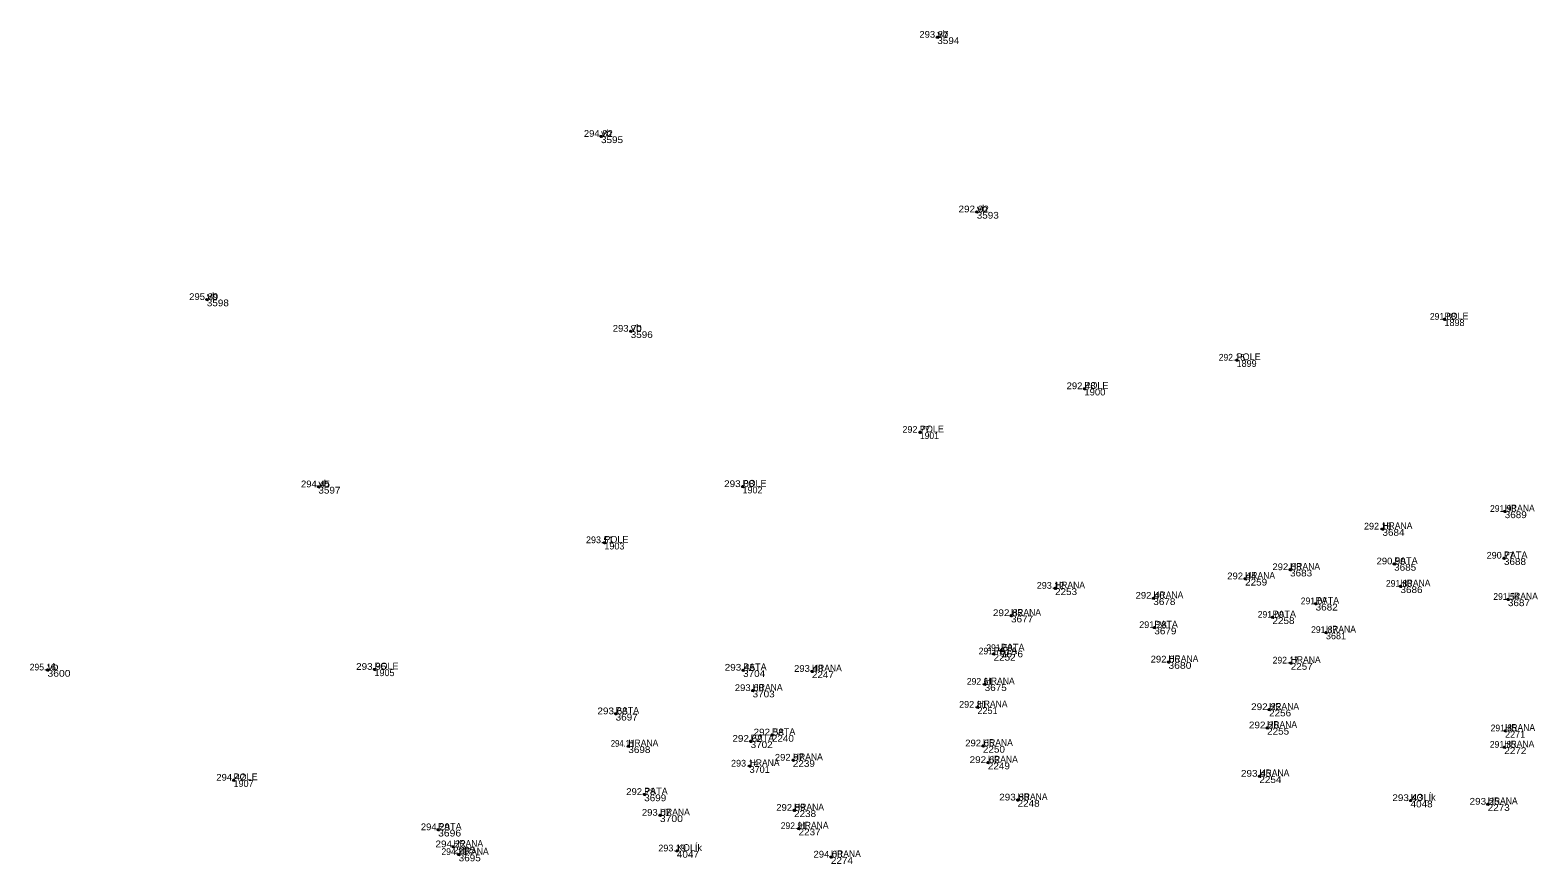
# Model space of a CAD drawing. Extents: x -565336 to -561834, y -1146819 to -1145270.
# Drawn here: x -563913.6 to -563837.5, y -1145806.3 to -1145764.2 of the extents above; entities that cross this region are included whole.
import ezdxf
from ezdxf.enums import TextEntityAlignment as Align

# ---------------------------------------------------------------- set-up
doc = ezdxf.new("R2010")
doc.units = 0
doc.header["$LTSCALE"] = 0.14
doc.header["$PDMODE"] = 32
doc.header["$PDSIZE"] = 0.07
for name, color, linetype in [('40', 7, 'Continuous'), ('43', 7, 'Continuous'), ('44', 7, 'Continuous'), ('45', 7, 'Continuous')]:
    doc.layers.add(name, color=color, linetype=linetype)

msp = doc.modelspace()

# ---------------------------------------------------------------- linework, layer by layer
at = {"layer": '40'}
for p in [(-563867.83, -1145764.59), (-563884.8, -1145769.59), (-563865.84, -1145773.4), (-563904.69, -1145777.82), (-563842.24, -1145778.82), (-563883.3, -1145779.42), (-563852.73, -1145780.88), (-563860.41, -1145782.32), (-563868.71, -1145784.52), (-563899.06, -1145787.27), (-563877.66, -1145787.26), (-563839.2, -1145788.51), (-563845.37, -1145789.4), (-563884.63, -1145790.09), (-563844.78, -1145791.16), (-563839.24, -1145790.87), (-563852.3, -1145791.91), (-563850.03, -1145791.45), (-563861.89, -1145792.39), (-563844.46, -1145792.29), (-563856.93, -1145792.89), (-563848.74, -1145793.17), (-563839.04, -1145792.95), (-563864.11, -1145793.77), (-563850.92, -1145793.85), (-563856.88, -1145794.37), (-563848.22, -1145794.62), (-563864.99, -1145795.7), (-563864.62, -1145795.53), (-563912.73, -1145796.51), (-563896.23, -1145796.48), (-563877.63, -1145796.52), (-563856.17, -1145796.11), (-563850, -1145796.16), (-563874.16, -1145796.58), (-563865.44, -1145797.23), (-563877.15, -1145797.55), (-563884.06, -1145798.72), (-563865.8, -1145798.39), (-563851.09, -1145798.51), (-563851.19, -1145799.43), (-563839.18, -1145799.58), (-563883.42, -1145800.36), (-563877.25, -1145800.11), (-563876.18, -1145799.79), (-563865.53, -1145800.34), (-563875.12, -1145801.06), (-563839.22, -1145800.41), (-563877.3, -1145801.36), (-563865.28, -1145801.18), (-563851.58, -1145801.87), (-563903.34, -1145802.07), (-563882.62, -1145802.79), (-563863.78, -1145803.07), (-563843.95, -1145803.1), (-563840.06, -1145803.28), (-563881.83, -1145803.84), (-563875.06, -1145803.59), (-563893.02, -1145804.57), (-563874.83, -1145804.51), (-563892.26, -1145805.43), (-563880.97, -1145805.64), (-563891.98, -1145805.82), (-563873.2, -1145805.95)]:
    msp.add_point(p, dxfattribs=at)

# ---------------------------------------------------------------- texts
at = {"layer": '43'}
for s, width, p in [('3594', 1.1, (-563867.83, -1145764.93)), ('3595', 1.1, (-563884.8, -1145769.93)), ('3593', 1.1, (-563865.84, -1145773.74)), ('3598', 1.1, (-563904.69, -1145778.16)), ('3596', 1.1, (-563883.3, -1145779.76)), ('1900', 1.05, (-563860.41, -1145782.66)), ('1901', 0.95, (-563868.71, -1145784.86)), ('3597', 1.1, (-563899.06, -1145787.61)), ('3689', 1.1, (-563839.2, -1145788.85)), ('3684', 1.1, (-563845.37, -1145789.74)), ('3685', 1.1, (-563844.78, -1145791.5)), ('3688', 1.1, (-563839.24, -1145791.21)), ('2259', 1.1, (-563852.3, -1145792.25)), ('3683', 1.1, (-563850.03, -1145791.79)), ('2253', 1.1, (-563861.89, -1145792.73)), ('3686', 1.1, (-563844.46, -1145792.63)), ('3678', 1.1, (-563856.93, -1145793.23)), ('3682', 1.1, (-563848.74, -1145793.51)), ('3687', 1.1, (-563839.04, -1145793.29)), ('3677', 1.1, (-563864.11, -1145794.11)), ('2258', 1.1, (-563850.92, -1145794.19)), ('3679', 1.1, (-563856.88, -1145794.71)), ('2252', 1.1, (-563864.99, -1145796.04)), ('3676', 1.1, (-563864.62, -1145795.87)), ('3600', 1.15, (-563912.73, -1145796.85)), ('3704', 1.1, (-563877.63, -1145796.86)), ('3680', 1.15, (-563856.17, -1145796.45)), ('2257', 1.1, (-563850, -1145796.5)), ('2247', 1.1, (-563874.16, -1145796.92)), ('3675', 1.1, (-563865.44, -1145797.57)), ('3703', 1.1, (-563877.15, -1145797.89)), ('3697', 1.1, (-563884.06, -1145799.06)), ('2256', 1.1, (-563851.09, -1145798.85)), ('2255', 1.1, (-563851.19, -1145799.77)), ('3702', 1.1, (-563877.25, -1145800.45)), ('2240', 1.1, (-563876.18, -1145800.13)), ('3698', 1.1, (-563883.42, -1145800.7)), ('2239', 1.1, (-563875.12, -1145801.4)), ('2250', 1.1, (-563865.53, -1145800.68)), ('2272', 1.1, (-563839.22, -1145800.75)), ('2249', 1.1, (-563865.28, -1145801.52)), ('2254', 1.1, (-563851.58, -1145802.21)), ('3699', 1.1, (-563882.62, -1145803.13)), ('2248', 1.1, (-563863.78, -1145803.41)), ('4048', 1.1, (-563843.95, -1145803.44)), ('2273', 1.1, (-563840.06, -1145803.62)), ('3700', 1.15, (-563881.83, -1145804.18)), ('2238', 1.1, (-563875.06, -1145803.93)), ('3696', 1.15, (-563893.02, -1145804.91)), ('2237', 1.1, (-563874.83, -1145804.85)), ('2235', 1.1, (-563892.26, -1145805.77)), ('4047', 1.1, (-563880.97, -1145805.98)), ('3695', 1.1, (-563891.98, -1145806.16)), ('2274', 1.1, (-563873.2, -1145806.29))]:
    msp.add_text(s, height=0.34, dxfattribs=dict(at, width=width)).set_placement(p)
for s, p in [('1898', (-563842.24, -1145779.16)), ('1899', (-563852.73, -1145781.22)), ('1902', (-563877.66, -1145787.6)), ('1903', (-563884.63, -1145790.43)), ('3681', (-563848.22, -1145794.96)), ('1905', (-563896.23, -1145796.82)), ('2251', (-563865.8, -1145798.73)), ('2271', (-563839.18, -1145799.92)), ('3701', (-563877.3, -1145801.7)), ('1907', (-563903.34, -1145802.41))]:
    msp.add_text(s, height=0.34, dxfattribs=at).set_placement(p)
at = {"layer": '44'}
for s, width, p in [('293.87', 1.05, (-563868.0055, -1145764.614)), ('294.82', 1.05, (-563884.935, -1145769.614)), ('292.92', 1.1, (-563865.9955, -1145773.424)), ('295.89', 1.05, (-563904.8495, -1145777.844)), ('291.88', 0.95, (-563842.3165, -1145778.844)), ('293.70', 1.05, (-563883.4755, -1145779.444)), ('292.16', 0.95, (-563852.97, -1145780.904)), ('292.48', 1.05, (-563860.576, -1145782.344)), ('294.45', 1.05, (-563899.206, -1145787.294)), ('293.08', 1.1, (-563877.8235, -1145787.284)), ('291.98', 0.95, (-563839.2815, -1145788.534)), ('292.08', 1.05, (-563850.191, -1145791.474)), ('290.90', 1.05, (-563844.9355, -1145791.184)), ('292.44', 1.05, (-563852.47, -1145791.934)), ('292.40', 1.05, (-563857.095, -1145792.914)), ('291.80', 0.95, (-563844.535, -1145792.314)), ('291.54', 0.95, (-563839.1165, -1145792.974)), ('292.82', 1.1, (-563864.26, -1145793.794)), ('291.07', 0.95, (-563848.8285, -1145793.194)), ('291.09', 0.95, (-563851.0005, -1145793.874)), ('291.87', 0.95, (-563848.3085, -1145794.644)), ('291.78', 0.95, (-563865.08, -1145795.724)), ('291.59', 0.95, (-563864.6965, -1145795.554)), ('295.16', 0.95, (-563912.9645, -1145796.534)), ('293.95', 1.1, (-563896.3935, -1145796.504)), ('293.45', 1.1, (-563877.7935, -1145796.544)), ('293.48', 1.05, (-563874.3285, -1145796.604)), ('292.06', 1.05, (-563856.335, -1145796.134)), ('292.17', 0.95, (-563850.248, -1145796.184)), ('293.60', 1.05, (-563877.3175, -1145797.574)), ('292.61', 0.95, (-563865.68, -1145797.254)), ('293.63', 1.1, (-563884.2155, -1145798.744)), ('292.22', 1.1, (-563851.231, -1145798.534)), ('292.58', 1.1, (-563876.337, -1145799.814)), ('292.28', 1.1, (-563851.3415, -1145799.454)), ('291.85', 0.95, (-563839.251, -1145799.604)), ('294.11', 0.85, (-563883.7145, -1145800.384)), ('292.62', 1.1, (-563877.4055, -1145800.134)), ('292.65', 1.05, (-563865.691, -1145800.364)), ('291.85', 0.95, (-563839.291, -1145800.434)), ('292.97', 1.05, (-563875.2985, -1145801.084)), ('292.62', 1.1, (-563865.4355, -1145801.204)), ('294.42', 1.05, (-563903.4805, -1145802.094)), ('293.45', 1.1, (-563851.7435, -1145801.894)), ('292.78', 1.05, (-563882.7945, -1145802.814)), ('292.89', 1.05, (-563875.225, -1145803.614)), ('293.80', 1.1, (-563863.942, -1145803.094)), ('293.43', 1.1, (-563844.1055, -1145803.124)), ('293.25', 1.1, (-563840.2085, -1145803.304)), ('293.07', 1.05, (-563882.0055, -1145803.864)), ('294.29', 1.05, (-563893.1605, -1145804.594)), ('292.91', 0.95, (-563875.07, -1145804.534)), ('294.22', 1.1, (-563892.386, -1145805.454)), ('294.21', 0.95, (-563892.19, -1145805.844)), ('294.08', 1.05, (-563873.346, -1145805.974))]:
    msp.add_text(s, height=0.34, dxfattribs=dict(at, width=width)).set_placement(p, align=Align.CENTER)
for s, p in [('292.77', (-563868.8965, -1145784.544)), ('292.18', (-563845.606, -1145789.424)), ('293.51', (-563884.863, -1145790.114)), ('290.77', (-563839.417, -1145790.894)), ('293.12', (-563862.1175, -1145792.414)), ('291.28', (-563856.947, -1145794.394)), ('292.81', (-563866.0345, -1145798.414)), ('293.14', (-563877.5425, -1145801.384)), ('293.19', (-563881.2125, -1145805.664))]:
    msp.add_text(s, height=0.34, dxfattribs=at).set_placement(p, align=Align.CENTER)
at = {"layer": '45'}
for s, width, p in [('vb', 1.15, (-563867.83, -1145764.59)), ('vb', 1.15, (-563884.8, -1145769.59)), ('vb', 1.15, (-563865.84, -1145773.4)), ('vb', 1.15, (-563904.69, -1145777.82)), ('vb', 1.15, (-563883.3, -1145779.42)), ('vb', 1.15, (-563899.06, -1145787.27)), ('HRANA', 0.95, (-563839.2, -1145788.51)), ('HRANA', 0.95, (-563845.37, -1145789.4)), ('HRANA', 0.95, (-563850.03, -1145791.45)), ('HRANA', 0.95, (-563852.3, -1145791.91)), ('HRANA', 0.95, (-563844.46, -1145792.29)), ('HRANA', 0.95, (-563861.89, -1145792.39)), ('HRANA', 0.95, (-563856.93, -1145792.89)), ('HRANA', 0.95, (-563839.04, -1145792.95)), ('HRANA', 0.95, (-563864.11, -1145793.77)), ('HRANA', 0.95, (-563848.22, -1145794.62)), ('vb', 1.15, (-563912.73, -1145796.51)), ('HRANA', 0.95, (-563874.16, -1145796.58)), ('HRANA', 0.95, (-563856.17, -1145796.11)), ('HRANA', 0.95, (-563850, -1145796.16)), ('HRANA', 0.95, (-563877.15, -1145797.55)), ('HRANA', 0.95, (-563865.44, -1145797.23)), ('HRANA', 0.95, (-563865.8, -1145798.39)), ('HRANA', 0.95, (-563851.09, -1145798.51)), ('HRANA', 0.95, (-563851.19, -1145799.43)), ('HRANA', 0.95, (-563839.18, -1145799.58)), ('HRANA', 0.95, (-563883.42, -1145800.36)), ('HRANA', 0.95, (-563865.53, -1145800.34)), ('HRANA', 0.95, (-563839.22, -1145800.41)), ('HRANA', 0.95, (-563877.3, -1145801.36)), ('HRANA', 0.95, (-563875.12, -1145801.06)), ('HRANA', 0.95, (-563865.28, -1145801.18)), ('HRANA', 0.95, (-563851.58, -1145801.87)), ('HRANA', 0.95, (-563875.06, -1145803.59)), ('HRANA', 0.95, (-563863.78, -1145803.07)), ('HRANA', 0.95, (-563840.06, -1145803.28)), ('HRANA', 0.95, (-563881.83, -1145803.84)), ('HRANA', 0.95, (-563874.83, -1145804.51)), ('HRANA', 0.95, (-563892.26, -1145805.43)), ('HRANA', 0.95, (-563891.98, -1145805.82)), ('HRANA', 0.95, (-563873.2, -1145805.95))]:
    msp.add_text(s, height=0.34, dxfattribs=dict(at, width=width)).set_placement(p)
for s, p in [('POLE', (-563842.24, -1145778.82)), ('POLE', (-563852.73, -1145780.88)), ('POLE', (-563860.41, -1145782.32)), ('POLE', (-563868.71, -1145784.52)), ('POLE', (-563877.66, -1145787.26)), ('POLE', (-563884.63, -1145790.09)), ('PATA', (-563844.78, -1145791.16)), ('PATA', (-563839.24, -1145790.87)), ('PATA', (-563848.74, -1145793.17)), ('PATA', (-563856.88, -1145794.37)), ('PATA', (-563850.92, -1145793.85)), ('PATA', (-563864.99, -1145795.7)), ('PATA', (-563864.62, -1145795.53)), ('POLE', (-563896.23, -1145796.48)), ('PATA', (-563877.63, -1145796.52)), ('PATA', (-563884.06, -1145798.72)), ('PATA', (-563876.18, -1145799.79)), ('PATA', (-563877.25, -1145800.11)), ('POLE', (-563903.34, -1145802.07)), ('PATA', (-563882.62, -1145802.79)), ('KOLÍk', (-563843.95, -1145803.1)), ('PATA', (-563893.02, -1145804.57)), ('KOLÍk', (-563880.97, -1145805.64))]:
    msp.add_text(s, height=0.34, dxfattribs=at).set_placement(p)

doc.saveas('drawing.dxf')
